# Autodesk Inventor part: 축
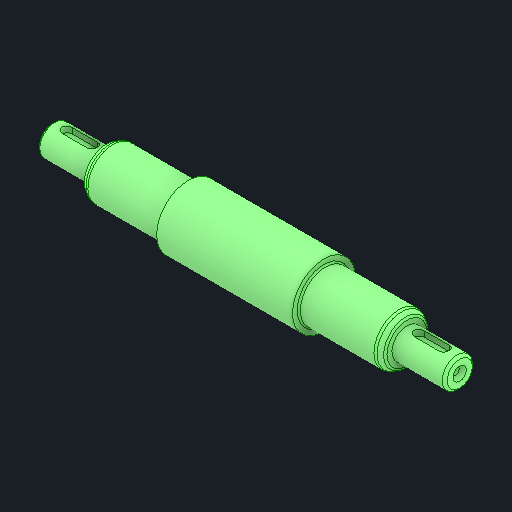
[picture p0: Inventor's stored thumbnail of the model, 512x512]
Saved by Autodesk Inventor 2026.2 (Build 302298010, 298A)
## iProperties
Created: 2026-03
Part Number: 축
Material: 강철, 탄소
Document SubType Name: Modeling
Designer: PC2-02
Density: 7.85 g/cm^3
Appearance: 기본값
Author: jhkim
Sending System: Autodesk Inventor 2026
Preprocessor: ST-DEVELOPER v20.1
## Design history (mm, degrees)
feature "솔리드1"
node "솔리드2"
